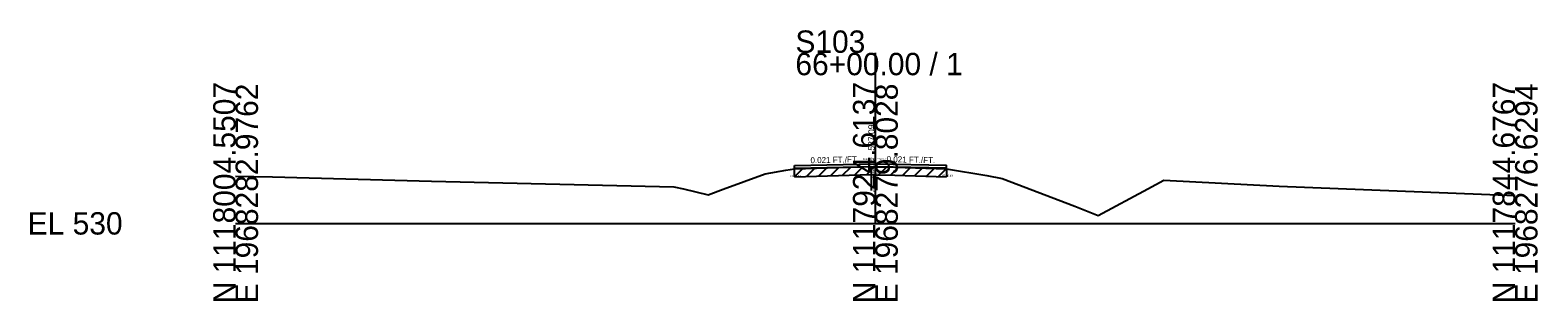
# Model space of a CAD drawing. Extents: x -26 to 163, y -10 to 24018.
# Drawn here: x -25.7 to 162.8, y 13990.3 to 14024.2 of the extents above; entities that cross this region are included whole.
import ezdxf

# ---------------------------------------------------------------- set-up
doc = ezdxf.new("R2010")
doc.units = 0
for name, color, linetype in [('RD_GPK_XS_Cell', 7, 'Continuous'), ('RD_XS_ExGround', 7, 'Continuous'), ('RD_XS_ExPaveRet', 7, 'Continuous'), ('RD_XS_Misc_Line', 7, 'Continuous'), ('RD_XS_PaveOvlay_CP', 7, 'Continuous'), ('RD_XS_TX_Elev_EX', 7, 'Continuous'), ('RD_XS_TX_ExEOP', 7, 'Continuous'), ('RD_XS_TX_Notes', 7, 'Continuous'), ('RD_XS_TX_Profile', 7, 'Continuous'), ('RD_XS_TX_Slope', 7, 'Continuous')]:
    doc.layers.add(name, color=color, linetype=linetype)

msp = doc.modelspace()

# ---------------------------------------------------------------- linework, layer by layer
at = {"layer": 'RD_GPK_XS_Cell'}
for p, q in [((80, 14000), (80, 14021.33)), ((0, 14000), (80, 14000)), ((80, 14000), (160, 14000))]:
    msp.add_line(p, q, dxfattribs=at)
at = {"layer": 'RD_XS_ExGround'}
msp.add_lwpolyline([(0, 14005.92), (4.61, 14005.82), (24.5, 14005.29), (54.79, 14004.58), (55.99, 14004.31), (59.07, 14003.59), (60.95, 14004.29), (66.22, 14006.21), (68.8, 14006.64), (69.9, 14006.82), (72.64, 14006.91), (79.46, 14007.11), (80, 14007.09), (82.42, 14007.02), (88.9, 14006.83), (93.92, 14005.98), (95.87, 14005.62), (104.94, 14002.15), (107.86, 14000.98), (114.09, 14004.33), (116.07, 14005.41), (130.51, 14004.66), (160, 14003.49)], dxfattribs=at)
at = {"layer": 'RD_XS_ExPaveRet'}
for p, q in [((69.9, 14005.82), (70.94, 14006.85)), ((69.9, 14005.82), (69.9, 14006.82)), ((71.4, 14005.87), (72.44, 14006.9)), ((72.64, 14005.91), (79.46, 14006.11)), ((72.9, 14005.92), (73.93, 14006.95)), ((74.4, 14005.96), (75.43, 14006.99)), ((75.9, 14006.01), (76.93, 14007.04)), ((77.4, 14006.05), (78.43, 14007.08)), ((78.9, 14006.09), (79.9, 14007.1)), ((79.46, 14006.11), (80, 14006.09)), ((80, 14006.09), (82.42, 14006.02)), ((80.4, 14006.08), (81.37, 14007.05)), ((81.9, 14006.03), (82.87, 14007)), ((83.4, 14005.99), (84.37, 14006.96)), ((84.9, 14005.94), (85.87, 14006.92)), ((86.4, 14005.9), (87.37, 14006.87)), ((87.9, 14005.86), (88.87, 14006.83)), ((88.9, 14006.83), (88.9, 14005.83)), ((69.9, 14005.82), (72.64, 14005.91)), ((82.42, 14006.02), (88.9, 14005.83))]:
    msp.add_line(p, q, dxfattribs=at)
at = {"layer": 'RD_XS_Misc_Line'}
msp.add_line((79.46, 14007.11), (79.46, 14004.11), dxfattribs=at)
at = {"layer": 'RD_XS_PaveOvlay_CP'}
for p, q in [((69.9, 14007.23), (80, 14007.44)), ((69.9, 14006.82), (69.9, 14007.23)), ((80, 14007.09), (69.9, 14006.88)), ((80, 14007.44), (88.9, 14007.26)), ((88.9, 14006.91), (80, 14007.09)), ((88.9, 14006.83), (88.9, 14007.26))]:
    msp.add_line(p, q, dxfattribs=at)

# ---------------------------------------------------------------- texts
at = {"layer": 'RD_GPK_XS_Cell'}
for s, p in [('S103', (70, 14021.33)), ('66+00.00 / 1', (70, 14018.53)), ('EL 530', (-26, 13998.6))]:
    msp.add_text(s, height=2.8, dxfattribs=at).set_placement(p)
for s, p in [('N 1118004.5507', (0, 13990)), ('N 1117924.6137', (80, 13990)), ('N 1117844.6767', (160, 13990)), ('E 1968282.9762', (2.8, 13990)), ('E 1968279.8028', (82.8, 13990)), ('E 1968276.6294', (162.8, 13990))]:
    msp.add_text(s, height=2.8, rotation=90, dxfattribs=at).set_placement(p)
at = {"layer": 'RD_XS_TX_Elev_EX'}
msp.add_text('537.09', height=0.8, rotation=90, dxfattribs=at).set_placement((79.9, 14009.09))
at = {"layer": 'RD_XS_TX_ExEOP'}
for s, p in [('EOP-L', (69.85, 14007.23)), ('EOP-R', (88.85, 14007.26))]:
    msp.add_text(s, height=0.1, rotation=270, dxfattribs=at).set_placement(p)
at = {"layer": 'RD_XS_TX_Notes'}
for s, p in [('Elev. @CL = 537.44', (78.47, 14007.94)), (' dE= 0.35', (79.29, 14006.09)), (' dE= 0.43', (88.2, 14005.83)), (' dE= 0.41', (69.2, 14005.82))]:
    msp.add_text(s, height=0.25, dxfattribs=at).set_placement(p)
msp.add_text(' Min. Distance @CP = -0.03', height=0.25, rotation=270, dxfattribs=at).set_placement((79.71, 14008.2))
at = {"layer": 'RD_XS_TX_Profile'}
msp.add_text('CL', height=0.25, dxfattribs=at).set_placement((79.77, 14007.44))
at = {"layer": 'RD_XS_TX_Slope'}
for rotation, p in [(1.1916, (71.89, 14007.52)), (358.8084, (81.4, 14007.66))]:
    msp.add_text('0.021 FT./FT.', height=0.75, rotation=rotation, dxfattribs=at).set_placement(p)

doc.saveas('drawing.dxf')
